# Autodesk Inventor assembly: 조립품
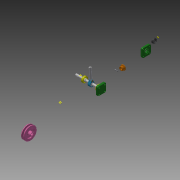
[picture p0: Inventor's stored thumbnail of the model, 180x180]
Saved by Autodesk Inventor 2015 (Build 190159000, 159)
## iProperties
Created: 2021-08
Part Number: 조립품
Document SubType Name: Assembly
Designer: 104-00
Author: 104-00
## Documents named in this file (16)
- C:\Users\104-00\Desktop\710806V1026\조립품.iam
- C:\Users\104-00\Desktop\710806V1026\V벨트풀리.ipt
- C:\Users\104-00\Desktop\710806V1026\고정핀 1.2x8.ipt
- C:\Users\104-00\Desktop\710806V1026\뒤커버.ipt
- C:\Users\104-00\Desktop\710806V1026\링크.ipt
- C:\Users\104-00\Desktop\710806V1026\멈춤나사 M3x8.ipt
- C:\Users\104-00\Desktop\710806V1026\베어링 12x32x10.ipt
- C:\Users\104-00\Desktop\710806V1026\본체.ipt
- C:\Users\104-00\Desktop\710806V1026\볼트 M4.ipt
- C:\Users\104-00\Desktop\710806V1026\부시.ipt
- C:\Users\104-00\Desktop\710806V1026\슬라이드.ipt
- C:\Users\104-00\Desktop\710806V1026\앞커버.ipt
- C:\Users\104-00\Desktop\710806V1026\오일 실 12 25 7.ipt
- C:\Users\104-00\Desktop\710806V1026\키 4x4x10.ipt
- C:\Users\104-00\Desktop\710806V1026\편심축.ipt
- C:\Users\104-00\Desktop\710806V1026\핀 5x18.ipt
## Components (3 placed, 3 different names)
1. V벨트풀리:1
2. 고정핀 1.2x8:1
3. 핀 5x18:1
